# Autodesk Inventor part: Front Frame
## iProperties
Created: 2009-03
Part Number: Front Frame
Document SubType Name: Modeling
Designer: tangg
Density: 7.86 g/cm^3
Material: Steel, Mild
Mass: 173.384 g
Surface Area: 347.527 cm^2
Volume: 22.059 cm^3
Author: tangg
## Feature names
1. Revolution1
2. Extrusion1
3. Extrusion2
4. Extrusion3
